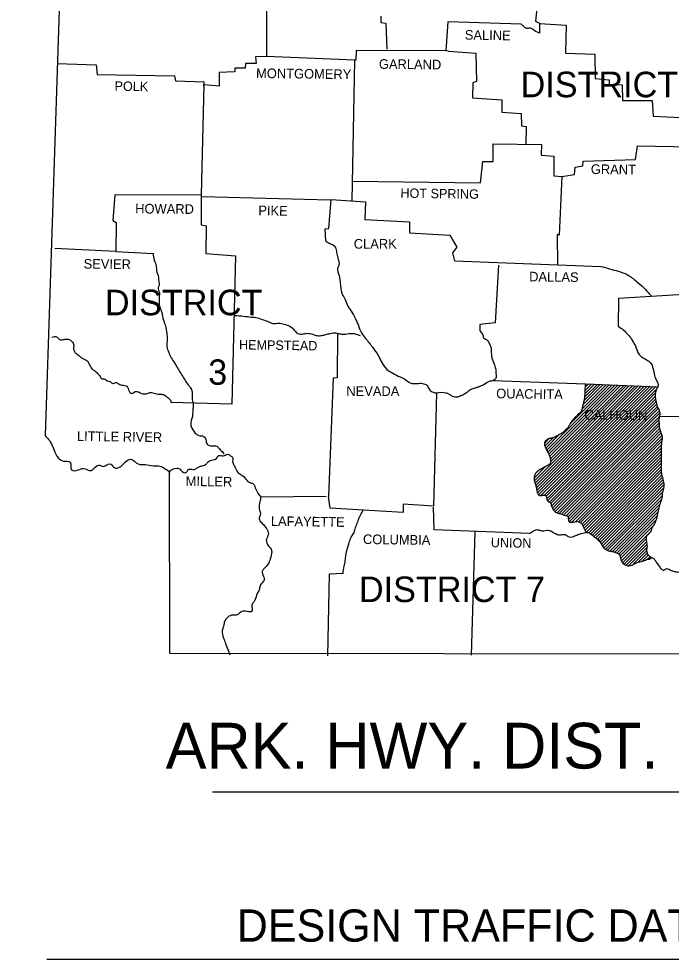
# Model space of a CAD drawing. Extents: x 1373094 to 1376427, y 1168361 to 1170494.
# Drawn here: x 1375691.4 to 1375995.2, y 1169546.2 to 1169984 of the extents above; entities that cross this region are included whole.
import ezdxf

# ---------------------------------------------------------------- set-up
doc = ezdxf.new("R2010")
doc.units = 0
for name, color, linetype in [('Default', 7, 'Continuous'), ('R_Border Notes', 7, 'Continuous'), ('R_Draft', 7, 'Continuous')]:
    doc.layers.add(name, color=color, linetype=linetype)

msp = doc.modelspace()

# ---------------------------------------------------------------- linework, layer by layer
at = {"layer": 'Default'}
for p, q in [((1375891.53, 1169968.91), (1375890.27, 1169969.12)), ((1375847.67, 1169964.84), (1375846.46, 1169899.27)), ((1375781.58, 1169624.07), (1376109.43, 1169624.07))]:
    msp.add_line(p, q, dxfattribs=at)
for points in [[(1375691.37, 1170246.85), (1375712.98, 1170073.32), (1375703.58, 1169790.06)], [(1375806.95, 1170027.49), (1375806.74, 1169966.41), (1375801.52, 1169966.3), (1375801.94, 1169963.17), (1375796.93, 1169963.28), (1375796.82, 1169960.98), (1375791.92, 1169960.98), (1375792.02, 1169959.31), (1375784.71, 1169959.1), (1375784.61, 1169952.73), (1375777.51, 1169953.36), (1375776.36, 1169901.99), (1375736.16, 1169902.09), (1375735.22, 1169890.19), (1375736.68, 1169889.14), (1375736.58, 1169875.78), (1375708.07, 1169877.03)], [(1375966.91, 1169997.52), (1375959.39, 1169998.36), (1375959.71, 1169995.54), (1375946.03, 1169995.02), (1375945.61, 1169990.94), (1375932.77, 1169990.21), (1375932.04, 1169982.9), (1375933.92, 1169981.96), (1375933.92, 1169977.3)], [(1375859.99, 1169985.2), (1375859.89, 1169982.38), (1375862.29, 1169981.96), (1375862.71, 1169969.85)], [(1375925.35, 1169981.55), (1375891.21, 1169982.59), (1375890.27, 1169969.12), (1375848.51, 1169969.33), (1375848.34, 1169964.82)], [(1375933.92, 1169981.91), (1375946.34, 1169981.13), (1375945.92, 1169968.08), (1375959.6, 1169967.56), (1375959.81, 1169956.18), (1375966.28, 1169955.65), (1375966.28, 1169953.67), (1375972.34, 1169953.25), (1375972.55, 1169945.94), (1375986.33, 1169945.94), (1375986.75, 1169938.74), (1375999.49, 1169938.11), (1375999.38, 1169924.52)], [(1375847.67, 1169964.84), (1375806.74, 1169966.41)], [(1375891.53, 1169968.91), (1375904.16, 1169967.97), (1375904.58, 1169954.82), (1375902.8, 1169954.19), (1375902.59, 1169947.2), (1375916.27, 1169946.26), (1375916.27, 1169940.51), (1375925.35, 1169939.99), (1375925.46, 1169934.25), (1375927.65, 1169933.94), (1375927.54, 1169925.69)], [(1375709.33, 1169963.17), (1375727.39, 1169962.54), (1375727.81, 1169958.16), (1375763.93, 1169957.43), (1375764.35, 1169955.13), (1375777.51, 1169954.71), (1375777.4, 1169952.73)], [(1375848.34, 1169964.82), (1375847.67, 1169964.84)], [(1375846.63, 1169908.46), (1375906.35, 1169907.63), (1375907.5, 1169917.54), (1375912.2, 1169917.54), (1375912.3, 1169925.9), (1375934.86, 1169925.58), (1375934.65, 1169920.57), (1375940.49, 1169920.15), (1375940.49, 1169910.97), (1375944.25, 1169910.65), (1375944.21, 1169909.7)], [(1375944.25, 1169910.65), (1375950.1, 1169911.49), (1375950.52, 1169915.04), (1375953.96, 1169915.66), (1375954.17, 1169917.75), (1375978.5, 1169918.48), (1375979.44, 1169924.85), (1376004.39, 1169924.44)], [(1375944.25, 1169910.65), (1375943, 1169883.3), (1375942.06, 1169883.61), (1375942.17, 1169869.41)], [(1375776.36, 1169901.99), (1375776.36, 1169888.1), (1375778.66, 1169887.68), (1375778.45, 1169874.74), (1375792.23, 1169873.69), (1375790.56, 1169804.68), (1375762.16, 1169805.41)], [(1375776.57, 1169901.26), (1375836.29, 1169899.69)], [(1375834.31, 1169880.58), (1375834.1, 1169886.33), (1375835.77, 1169886.43), (1375836.81, 1169899.9), (1375852.89, 1169898.85), (1375852.48, 1169890.61), (1375873.25, 1169889.46), (1375873.36, 1169884.45), (1375892.15, 1169883.3), (1375895.39, 1169877.66), (1375893.4, 1169875.15), (1375894.34, 1169871.29), (1375962.42, 1169868.79)], [(1375736.58, 1169875.78), (1375753.91, 1169874.74)], [(1375914.81, 1169869.31), (1375913.24, 1169842.47), (1375906.04, 1169841.64)], [(1375985.85, 1169854.8), (1375970.57, 1169853.85), (1375970.46, 1169840.8)], [(1376001.05, 1169855.73), (1375985.79, 1169854.79)], [(1375839.84, 1169837.67), (1375839.63, 1169816.89), (1375837.75, 1169816.68), (1375835.66, 1169761.66)], [(1375912.2, 1169815.64), (1375955.43, 1169814.07), (1375988.96, 1169812.76)], [(1375885.89, 1169809.79), (1375884.53, 1169757.17), (1375870.43, 1169758.11), (1375870.33, 1169754.25), (1375851.84, 1169755.33)], [(1375989.57, 1169798.94), (1376036.76, 1169799.04)], [(1375761.32, 1169773.25), (1375761.53, 1169688.78), (1376144.2, 1169688.16)], [(1375834.5, 1169761.65), (1375804.03, 1169761.35)], [(1375851.85, 1169755.33), (1375836.4, 1169756.23), (1375835.66, 1169761.66)], [(1375929.32, 1169744.43), (1375884.74, 1169746.1), (1375884.53, 1169756.65)], [(1375903.74, 1169745.16), (1375902.07, 1169687.84)], [(1375842.35, 1169725.85), (1375835.87, 1169725.43), (1375835.14, 1169687.53)]]:
    msp.add_lwpolyline(points, dxfattribs=at)
for points in [[(1375933.92, 1169977.3), (1375931.2, 1169978.73), (1375929.64, 1169979.67), (1375927.97, 1169979.56), (1375926.61, 1169980.4), (1375925.35, 1169981.55)], [(1375834.31, 1169880.58), (1375835.98, 1169879.54), (1375837.96, 1169878.6), (1375839.01, 1169877.03), (1375839.42, 1169874.63), (1375840.15, 1169872.02), (1375840.36, 1169869.31), (1375839.74, 1169867.85), (1375840.57, 1169864.5), (1375840.89, 1169862.21), (1375841.2, 1169859.49), (1375842.03, 1169855.84), (1375843.39, 1169853.33), (1375844.64, 1169850.3), (1375846.73, 1169847.07), (1375848.51, 1169843.52), (1375849.34, 1169841.64), (1375850.91, 1169837.78), (1375852.89, 1169835.17), (1375856.03, 1169831.2), (1375858.84, 1169827.13), (1375860.41, 1169824.1), (1375862.81, 1169820.76), (1375865.53, 1169819.09), (1375868.97, 1169817.31), (1375871.17, 1169816.27), (1375873.67, 1169814.49), (1375876.91, 1169814.28), (1375879.31, 1169814.28), (1375881.5, 1169813.34), (1375882.55, 1169811.46), (1375884.43, 1169810.21), (1375885.89, 1169809.79)], [(1375753.91, 1169874.74), (1375754.43, 1169871.6), (1375755.37, 1169868.89), (1375755.48, 1169866.8), (1375756.42, 1169863.67), (1375756.42, 1169862.52), (1375756.73, 1169860.22), (1375756.31, 1169858.97), (1375756.83, 1169856.46), (1375756.73, 1169854.59), (1375756.73, 1169853.02), (1375756.83, 1169850.41), (1375757.67, 1169848.11), (1375758.5, 1169844.67), (1375759.03, 1169842.89), (1375759.86, 1169840.18), (1375760.38, 1169836.84), (1375760.49, 1169834.33), (1375760.28, 1169832.03), (1375760.91, 1169829.42), (1375762.05, 1169826.81), (1375763.52, 1169824.31), (1375765.29, 1169821.49), (1375766.54, 1169819.3), (1375768.11, 1169816.89), (1375769.36, 1169814.91), (1375771.24, 1169812.4), (1375772.08, 1169810.32), (1375772.08, 1169807.39), (1375772.5, 1169804.68), (1375772.39, 1169801.65), (1375772.18, 1169798.94), (1375771.45, 1169795.18), (1375771.97, 1169793.4), (1375773.96, 1169790.79), (1375775.21, 1169790.06), (1375777.4, 1169789.64), (1375778.45, 1169788.18), (1375779.07, 1169785.99), (1375781.27, 1169785.26), (1375783.67, 1169785.05), (1375784.82, 1169783.8), (1375786.38, 1169782.13), (1375786.9, 1169781.29)], [(1375962.42, 1169868.79), (1375970.57, 1169866.49), (1375974.74, 1169864.92), (1375978.92, 1169861.89), (1375982.36, 1169858.87), (1375985.81, 1169855)], [(1375792.02, 1169845.92), (1375795.99, 1169845.61), (1375799.64, 1169845.19), (1375802.46, 1169844.88), (1375805.39, 1169843.83), (1375808, 1169842.89), (1375809.67, 1169842.16), (1375812.49, 1169842.37), (1375814.89, 1169841.85), (1375817.6, 1169840.91), (1375819.59, 1169839.13), (1375820.84, 1169837.78), (1375823.24, 1169837.25), (1375825.22, 1169837.57), (1375827.63, 1169837.36), (1375830.34, 1169836.52), (1375832.53, 1169836.63), (1375834.31, 1169837.04), (1375836.4, 1169837.57), (1375839.01, 1169837.78), (1375840.99, 1169837.36), (1375843.6, 1169837.25), (1375846.63, 1169837.57), (1375850.39, 1169836.52)], [(1375906.04, 1169841.64), (1375906.04, 1169839.65), (1375906.77, 1169837.78), (1375907.5, 1169836.94), (1375907.81, 1169835.58), (1375908.75, 1169834.96), (1375910.11, 1169833.7), (1375910.84, 1169831.93), (1375911.36, 1169830.78), (1375911.36, 1169829.32), (1375911.47, 1169827.86), (1375911.68, 1169826.08), (1375912.93, 1169822.95), (1375913.24, 1169821.7), (1375913.45, 1169820.65), (1375913.56, 1169818.88), (1375913.56, 1169816.79), (1375912.2, 1169815.64)], [(1375970.46, 1169840.8), (1375972.86, 1169839.24), (1375974.85, 1169837.15), (1375976.31, 1169835.58), (1375977.25, 1169833.81), (1375978.5, 1169831.72), (1375980.28, 1169827.75), (1375981.84, 1169826.39), (1375984.03, 1169825.04), (1375985.39, 1169824.1), (1375986.75, 1169821.07), (1375987.38, 1169818.04), (1375988.52, 1169815.33), (1375989.05, 1169813.24), (1375988.11, 1169811.15), (1375987.9, 1169806.97), (1375988.52, 1169804.16), (1375989.36, 1169802.07), (1375989.88, 1169799.67), (1375989.57, 1169798.94)], [(1375706.82, 1169835.79), (1375709.12, 1169835.9), (1375710.68, 1169834.54), (1375711.62, 1169834.64), (1375713.29, 1169834.85), (1375714.86, 1169834.75), (1375716.01, 1169833.81), (1375716.95, 1169832.14), (1375716.84, 1169830.57), (1375716.95, 1169829.94), (1375717.68, 1169828.59), (1375718.93, 1169827.54), (1375720.29, 1169826.5), (1375721.54, 1169825.66), (1375723.63, 1169824.31), (1375723.84, 1169823.89), (1375724.68, 1169822.22), (1375725.72, 1169820.86), (1375726.97, 1169820.03), (1375728.33, 1169818.56), (1375728.96, 1169817.94), (1375730, 1169816.48), (1375731.15, 1169816.37), (1375732.71, 1169815.43), (1375733.86, 1169815.12), (1375735.12, 1169814.28), (1375736.37, 1169814.7), (1375737.94, 1169814.07), (1375740.02, 1169813.45), (1375741.17, 1169813.24), (1375742.53, 1169811.26), (1375743.89, 1169809.59), (1375745.56, 1169810.52), (1375748.69, 1169809.59), (1375750.67, 1169809.48), (1375752.45, 1169810), (1375753.81, 1169809.9), (1375756.31, 1169809.27), (1375757.88, 1169809.27), (1375759.55, 1169808.65), (1375761.11, 1169807.39), (1375762.16, 1169806.04), (1375762.16, 1169805.41)], [(1375907.5, 1169813.45), (1375906.75, 1169813.14), (1375905.41, 1169812.61), (1375903.85, 1169812.09), (1375902.38, 1169811.67), (1375900.5, 1169810.42), (1375899.04, 1169809.38), (1375897.06, 1169808.44), (1375895.18, 1169807.81), (1375892.88, 1169808.54), (1375891.63, 1169809.27), (1375890.27, 1169809.79), (1375885.89, 1169809.79)], [(1375907.5, 1169813.45), (1375910.22, 1169815.22), (1375913.24, 1169815.64)], [(1375955.07, 1169814.09), (1375955.01, 1169810.84), (1375954.93, 1169809.22), (1375954.88, 1169808.41), (1375954.8, 1169807.6), (1375954.48, 1169805.97), (1375954.07, 1169804.36), (1375953.79, 1169802.88), (1375953.61, 1169802.15), (1375953.49, 1169801.79), (1375953.42, 1169801.62), (1375953.34, 1169801.44), (1375953.02, 1169800.96), (1375952.62, 1169800.54), (1375951.77, 1169799.77), (1375950.93, 1169798.94), (1375950.1, 1169798.1), (1375948.53, 1169796.22), (1375948.17, 1169795.66), (1375947.86, 1169795.07), (1375947.54, 1169794.48), (1375947.18, 1169793.92), (1375945.82, 1169792.46), (1375944.04, 1169791), (1375942.27, 1169789.96), (1375940.29, 1169789.02), (1375939.75, 1169788.85), (1375939.2, 1169788.74), (1375938.64, 1169788.64), (1375938.09, 1169788.49), (1375937.23, 1169788.06), (1375936.85, 1169787.74), (1375936.68, 1169787.55), (1375936.53, 1169787.35), (1375936.25, 1169786.74), (1375936.16, 1169786.09), (1375936.42, 1169784.84), (1375936.85, 1169783.95), (1375937.31, 1169783.07), (1375937.78, 1169782.19), (1375938.2, 1169781.29), (1375938.82, 1169779.62), (1375938.96, 1169779.13), (1375939.05, 1169778.63), (1375939.08, 1169778.13), (1375939.03, 1169777.64), (1375938.3, 1169776.49), (1375936.63, 1169775.55), (1375934.65, 1169774.4), (1375932.87, 1169773.35), (1375932.45, 1169773.02), (1375932.11, 1169772.59), (1375931.84, 1169772.1), (1375931.62, 1169771.58), (1375931.34, 1169770.38), (1375931.41, 1169769.18), (1375931.6, 1169768.47), (1375931.83, 1169767.77), (1375932.05, 1169767.07), (1375932.25, 1169766.36), (1375932.4, 1169765.53), (1375932.56, 1169764.69), (1375932.96, 1169763.21), (1375933.33, 1169762.56), (1375933.59, 1169762.3), (1375933.74, 1169762.18), (1375933.92, 1169762.08), (1375934.18, 1169762.02), (1375934.44, 1169762.06), (1375934.7, 1169762.14), (1375934.96, 1169762.18), (1375935.2, 1169762.2), (1375935.43, 1169762.23), (1375935.9, 1169762.3), (1375936.37, 1169762.28), (1375936.61, 1169762.21), (1375936.72, 1169762.15), (1375936.84, 1169762.08), (1375937, 1169761.84), (1375937.05, 1169761.56), (1375937.15, 1169761.03), (1375937.57, 1169759.68), (1375937.88, 1169759.33), (1375938.35, 1169759.1), (1375938.82, 1169758.87), (1375939.14, 1169758.53), (1375939.21, 1169758.28), (1375939.25, 1169758.01), (1375939.28, 1169757.74), (1375939.35, 1169757.48), (1375939.74, 1169756.47), (1375940.29, 1169755.5), (1375940.62, 1169755.08), (1375940.99, 1169754.7), (1375941.85, 1169754.14), (1375943, 1169753.73), (1375945.4, 1169753), (1375946.65, 1169752.68), (1375946.83, 1169752.6), (1375947.16, 1169752.09), (1375947.32, 1169751.08), (1375947.49, 1169750.12), (1375947.68, 1169749.79), (1375948.01, 1169749.65), (1375948.85, 1169749.66), (1375949.68, 1169749.76), (1375950.94, 1169749.97), (1375951.99, 1169749.92), (1375952.51, 1169749.74), (1375952.77, 1169749.61), (1375953.02, 1169749.45), (1375953.58, 1169748.86), (1375953.96, 1169748.19), (1375954.21, 1169747.68), (1375954.43, 1169747.15), (1375954.65, 1169746.62), (1375954.9, 1169746.1), (1375955.45, 1169745.31), (1375955.79, 1169744.96), (1375955.99, 1169744.77)], [(1375989.57, 1169798.94), (1375989.99, 1169792.46), (1375990.93, 1169789.33), (1375990.61, 1169785.99), (1375990.51, 1169782.75), (1375990.51, 1169779.83), (1375990.51, 1169777.01), (1375990.51, 1169774.09), (1375990.72, 1169772), (1375991.45, 1169768.97), (1375991.76, 1169766.15), (1375991.13, 1169763.44), (1375990.82, 1169760.93), (1375989.99, 1169758.42), (1375989.25, 1169755.61), (1375988.42, 1169751.95), (1375987.69, 1169749.55), (1375986.23, 1169747.04), (1375985.29, 1169744.75), (1375983.83, 1169743.29), (1375983.62, 1169740.78), (1375983.93, 1169738.48), (1375983.72, 1169736.39), (1375984.45, 1169734.41), (1375986.33, 1169733.05)], [(1375703.58, 1169790.06), (1375706.61, 1169786.09), (1375707.86, 1169783.27), (1375709.64, 1169779.62), (1375712.25, 1169778.16), (1375715.28, 1169777.64), (1375715.9, 1169774.09), (1375719.04, 1169773.98), (1375721.54, 1169774.71), (1375724.99, 1169773.77), (1375728.64, 1169776.28), (1375730.73, 1169775.65), (1375733.76, 1169776.9), (1375736.06, 1169775.03), (1375740.02, 1169776.7), (1375743.57, 1169778.99), (1375746.91, 1169776.8), (1375750.15, 1169776.49), (1375754.01, 1169775.97), (1375757.04, 1169775.76), (1375759.76, 1169774.4), (1375761.74, 1169773.04), (1375761.32, 1169773.25)], [(1375761.32, 1169773.25), (1375764.98, 1169774.82), (1375766.54, 1169774.29), (1375767.9, 1169772.94), (1375769.47, 1169772.94), (1375770.3, 1169774.19), (1375771.87, 1169774.29), (1375773.12, 1169774.19), (1375774.48, 1169775.03), (1375775.63, 1169775.55), (1375777.19, 1169776.07), (1375778.34, 1169776.49), (1375779.39, 1169777.64), (1375781.27, 1169778.58), (1375783.46, 1169779.31), (1375784.09, 1169780.35), (1375785.13, 1169780.77), (1375787.22, 1169780.66), (1375788.58, 1169781.29), (1375789.72, 1169780.77), (1375790.77, 1169780.04), (1375790.98, 1169777.32), (1375791.81, 1169775.86), (1375793.06, 1169773.25), (1375794.84, 1169771.89), (1375796.51, 1169770.54), (1375797.14, 1169769.7), (1375798.91, 1169768.13), (1375800.48, 1169767.61), (1375801.21, 1169766.46), (1375802.36, 1169763.75), (1375804.03, 1169761.35)], [(1375804.03, 1169761.35), (1375803.4, 1169758.32), (1375803.3, 1169755.92), (1375803.82, 1169753.1), (1375803.3, 1169751.74), (1375804.13, 1169749.76), (1375805.7, 1169748.19), (1375806.85, 1169746.52), (1375807.58, 1169744.12), (1375806.64, 1169741.41), (1375807.68, 1169738.59), (1375808.62, 1169737.54), (1375809.14, 1169735.87), (1375808.41, 1169732.64), (1375807.47, 1169730.23), (1375805.39, 1169727.83), (1375804.76, 1169726.68), (1375805.07, 1169725.12), (1375805.59, 1169722.61), (1375805.07, 1169721.88), (1375803.71, 1169720.11), (1375803.3, 1169718.12), (1375802.36, 1169716.45), (1375801.31, 1169713.42), (1375799.96, 1169710.92), (1375799.75, 1169708.1), (1375797.66, 1169708.1), (1375795.26, 1169708.1), (1375793.06, 1169706.53), (1375791.08, 1169706.43), (1375788.68, 1169705.49), (1375787.22, 1169703.51), (1375786.7, 1169701.31), (1375786.07, 1169699.22), (1375786.7, 1169695.67), (1375787.64, 1169693.17), (1375788.37, 1169691.18), (1375789.62, 1169687.95)], [(1375842.35, 1169725.85), (1375842.87, 1169729.19), (1375843.39, 1169731.8), (1375843.7, 1169734.31), (1375844.33, 1169737.12), (1375845.27, 1169740.15), (1375846.11, 1169742.66), (1375847.25, 1169744.43), (1375847.99, 1169746.52), (1375848.93, 1169749.03), (1375849.86, 1169751.64), (1375851.74, 1169755.32)], [(1375929.32, 1169744.43), (1375930.99, 1169745.58), (1375932.56, 1169746.21), (1375934.13, 1169745.9), (1375935.8, 1169745.69), (1375937.26, 1169745.9), (1375939.14, 1169745.58), (1375940.7, 1169744.64), (1375942.48, 1169743.91), (1375944.25, 1169743.91), (1375945.82, 1169743.91), (1375947.18, 1169742.97), (1375949.68, 1169743.08), (1375951.77, 1169743.91), (1375953.86, 1169744.54), (1375956.68, 1169744.85), (1375959.18, 1169743.08), (1375960.96, 1169741.61), (1375962.42, 1169739.94), (1375963.47, 1169738.06), (1375964.61, 1169737.02), (1375966.49, 1169736.29), (1375967.95, 1169735.98), (1375969.73, 1169735.45), (1375970.67, 1169735.04), (1375971.5, 1169733.05), (1375972.86, 1169730.34), (1375975.47, 1169729.4), (1375978.71, 1169730.65), (1375981.32, 1169731.38), (1375983.2, 1169732.01), (1375984.35, 1169732.43), (1375985.39, 1169732.53), (1375985.08, 1169732.74), (1375986.33, 1169733.05), (1375987.48, 1169732.22), (1375988.21, 1169731.07), (1375989.46, 1169729.4), (1375990.61, 1169727.94), (1375991.76, 1169727.41), (1375992.91, 1169728.04), (1375994.48, 1169727.52), (1375995.83, 1169727), (1375997.4, 1169726.58), (1375998.76, 1169726.48), (1376000.53, 1169726.06), (1376001.89, 1169725.33), (1376003.14, 1169724.6), (1376004.39, 1169723.24), (1376005.65, 1169721.15), (1376006.07, 1169719.48), (1376007.53, 1169717.81), (1376008.88, 1169717.81), (1376010.87, 1169715.09), (1376011.6, 1169714.05), (1376013.17, 1169712.17), (1376014.31, 1169712.17), (1376016.51, 1169711.75)]]:
    msp.add_spline(points, degree=3, dxfattribs=at)
at = {"layer": 'R_Border Notes'}
for p, q in [((1375931.46, 1169768.96), (1375975.78, 1169813.28)), ((1375931.79, 1169767.87), (1375977.15, 1169813.23)), ((1375932.14, 1169766.8), (1375978.51, 1169813.17)), ((1375932.38, 1169765.63), (1375979.87, 1169813.12)), ((1375932.61, 1169764.45), (1375981.23, 1169813.07)), ((1375932.92, 1169763.34), (1375982.59, 1169813.01)), ((1375933.43, 1169762.44), (1375983.95, 1169812.96)), ((1375937.24, 1169783.22), (1375967.62, 1169813.6)), ((1375937.73, 1169782.29), (1375968.98, 1169813.54)), ((1375938.18, 1169781.33), (1375970.34, 1169813.49)), ((1375938.58, 1169780.32), (1375971.7, 1169813.44)), ((1375938.93, 1169779.25), (1375973.06, 1169813.39)), ((1375939.07, 1169777.98), (1375974.42, 1169813.33)), ((1375948.06, 1169795.46), (1375966.26, 1169813.65)), ((1375953.71, 1169802.52), (1375964.9, 1169813.7)), ((1375954.05, 1169804.27), (1375963.53, 1169813.76)), ((1375954.53, 1169806.16), (1375962.17, 1169813.81)), ((1375954.83, 1169807.88), (1375960.81, 1169813.86)), ((1375954.94, 1169809.41), (1375959.45, 1169813.92)), ((1375955.01, 1169810.89), (1375958.09, 1169813.97)), ((1375955.04, 1169812.33), (1375956.73, 1169814.02)), ((1375955.07, 1169813.77), (1375955.37, 1169814.08)), ((1375934.48, 1169762.07), (1375985.31, 1169812.91)), ((1375936.13, 1169762.31), (1375986.67, 1169812.85)), ((1375937.01, 1169761.78), (1375988.03, 1169812.8)), ((1375937.25, 1169760.61), (1375988.28, 1169811.63)), ((1375937.63, 1169759.57), (1375987.92, 1169809.86)), ((1375938.5, 1169759.03), (1375987.82, 1169808.34)), ((1375939.2, 1169758.31), (1375987.89, 1169807)), ((1375939.46, 1169757.15), (1375988.1, 1169805.79)), ((1375939.89, 1169756.17), (1375988.37, 1169804.65)), ((1375940.43, 1169755.3), (1375988.73, 1169803.6)), ((1375941.13, 1169754.58), (1375989.15, 1169802.6)), ((1375942.03, 1169754.07), (1375989.53, 1169801.57)), ((1375943.08, 1169753.7), (1375989.8, 1169800.43)), ((1375944.16, 1169753.37), (1375989.57, 1169798.79)), ((1375945.24, 1169753.04), (1375989.64, 1169797.44)), ((1375946.37, 1169752.75), (1375989.72, 1169796.1)), ((1375947.15, 1169752.12), (1375989.81, 1169794.78)), ((1375947.35, 1169750.9), (1375989.9, 1169793.46)), ((1375947.67, 1169749.81), (1375990.03, 1169792.17)), ((1375948.95, 1169749.67), (1375990.4, 1169791.12)), ((1375936.17, 1169786.39), (1375938.35, 1169788.58)), ((1375936.32, 1169785.13), (1375940.16, 1169788.97)), ((1375936.75, 1169784.14), (1375942.91, 1169790.31)), ((1375950.61, 1169749.92), (1375990.8, 1169790.11)), ((1375952.01, 1169749.91), (1375990.9, 1169788.8)), ((1375952.99, 1169749.47), (1375990.72, 1169787.21)), ((1375953.66, 1169748.73), (1375990.6, 1169785.66)), ((1375954.15, 1169747.81), (1375990.53, 1169784.19)), ((1375954.57, 1169746.81), (1375990.51, 1169782.75)), ((1375955.04, 1169745.87), (1375990.51, 1169781.33)), ((1375955.67, 1169745.08), (1375990.51, 1169779.92)), ((1375956.8, 1169744.79), (1375990.51, 1169778.51)), ((1375931.33, 1169770.24), (1375936.65, 1169775.56)), ((1375931.9, 1169772.22), (1375933.26, 1169773.59)), ((1375957.68, 1169744.27), (1375990.51, 1169777.09)), ((1375958.48, 1169743.65), (1375990.51, 1169775.68)), ((1375959.26, 1169743.02), (1375990.51, 1169774.26)), ((1375960.05, 1169742.39), (1375990.58, 1169772.92)), ((1375960.82, 1169741.74), (1375990.77, 1169771.7)), ((1375961.53, 1169741.05), (1375991.05, 1169770.56)), ((1375962.18, 1169740.27), (1375991.34, 1169769.44)), ((1375962.74, 1169739.42), (1375991.59, 1169768.27)), ((1375963.21, 1169738.47), (1375991.76, 1169767.03)), ((1375963.81, 1169737.66), (1375991.67, 1169765.52)), ((1375964.59, 1169737.03), (1375991.16, 1169763.61)), ((1375965.56, 1169736.58), (1375990.99, 1169762.01)), ((1375966.64, 1169736.25), (1375990.6, 1169760.22)), ((1375967.82, 1169736.01), (1375989.89, 1169758.09)), ((1375968.91, 1169735.7), (1375989.4, 1169756.18)), ((1375970.01, 1169735.38), (1375988.96, 1169754.33)), ((1375970.84, 1169734.8), (1375988.55, 1169752.51)), ((1375971.24, 1169733.79), (1375988.05, 1169750.59)), ((1375971.63, 1169732.76), (1375986.68, 1169747.81)), ((1375972, 1169731.71), (1375985.49, 1169745.2)), ((1375972.49, 1169730.79), (1375983.59, 1169741.89)), ((1375973.17, 1169730.06), (1375983.64, 1169740.53)), ((1375974.05, 1169729.52), (1375983.83, 1169739.3)), ((1375975.31, 1169729.36), (1375983.91, 1169737.97)), ((1375977.59, 1169730.24), (1375983.72, 1169736.36)), ((1375979.71, 1169730.93), (1375983.98, 1169735.21)), ((1375981.69, 1169731.5), (1375984.52, 1169734.33)), ((1375983.85, 1169732.25), (1375985.18, 1169733.58))]:
    msp.add_line(p, q, dxfattribs=at)
at = {"layer": 'R_Draft'}
msp.add_line((1375704.42, 1169546.23), (1376169.6, 1169546.23), dxfattribs=at)

# ---------------------------------------------------------------- texts
at = {"layer": 'Default'}
for s, height, rotation, p in [('SALINE', 4.49, 359.1492, (1375899.04, 1169974.34)), ('GARLAND', 4.49, 359.3658, (1375859.05, 1169960.77)), ('MONTGOMERY', 4.49, 359.2944, (1375801.84, 1169956.49)), ('POLK', 4.384, 359.2152, (1375735.95, 1169950.54)), ('GRANT', 4.49, 359.4032, (1375957.72, 1169911.8)), ('HOT SPRING', 4.386, 359.2216, (1375869.08, 1169900.73)), ('HOWARD', 4.49, 359.5145, (1375745.56, 1169893.43)), ('PIKE', 4.489, 359.0452, (1375802.88, 1169892.59)), ('SEVIER', 4.49, 359.4271, (1375721.54, 1169867.74)), ('DALLAS', 4.489, 359.2462, (1375929.01, 1169861.79)), ('HEMPSTEAD', 4.384, 359.1885, (1375793.9, 1169830.15)), ('OUACHITA', 4.49, 359.2043, (1375913.66, 1169807.39)), ('CALHOUN', 4.49, 359.3634, (1375954.69, 1169797.47)), ('LITTLE RIVER', 4.4903, 359.1697, (1375718.41, 1169787.55)), ('MILLER', 4.489, 359.132, (1375769.05, 1169766.57)), ('LAFAYETTE', 4.489, 359.1839, (1375808.73, 1169747.98)), ('COLUMBIA', 4.489, 359.2125, (1375851.64, 1169739.53)), ('UNION', 4.386, 358.9584, (1375911.15, 1169738.06))]:
    msp.add_text(s, height=height, rotation=rotation, dxfattribs=at).set_placement(p)
for s, height, p in [('DISTRICT 6', 11.903, (1375925.04, 1169947.51)), ('CLARK', 4.49, (1375847.36, 1169877.03)), ('DISTRICT', 11.903, (1375731.46, 1169846.02)), ('3', 11.8, (1375779.6, 1169813.66)), ('NEVADA', 4.49, (1375843.91, 1169808.44)), ('DISTRICT 7', 11.903, (1375849.76, 1169712.48)), ('  ARK. HWY. DIST. NO. 7', 21.2995, (1375743.95, 1169634.99))]:
    msp.add_text(s, height=height, dxfattribs=at).set_placement(p)
at = {"layer": 'R_Draft'}
msp.add_text('DESIGN TRAFFIC DATA', height=15, dxfattribs=at).set_placement((1375792.83, 1169554.39))

doc.saveas('drawing.dxf')
